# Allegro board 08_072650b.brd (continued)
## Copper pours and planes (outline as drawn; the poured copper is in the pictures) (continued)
UNNAMED_41_ADLTM4709_I15_VIN11 on TOP: 190.14,220.27 197.49,220.27 198.15,220.93 198.15,222.68 197.76,223.06 196.42,223.06 195.43,222.1 193.65,222.1 193.24,221.69 191.85,221.69 191.08,222.45 190.91,222.68 190.27,222.68 189.89,222.3 189.89,220.52
UNNAMED_41_ADLTM4709_I15_VIN11 on BOTTOM: 189.76,222.43 190.02,222.68 190.91,222.68 191.8,221.79 193.19,221.79 193.45,221.54 193.45,220.27 193.19,220.01 190.14,220.01 189.76,220.4
UNNAMED_41_ADLTM4709_I15_VIN21 on TOP: 191.29,218.62 191.29,217.98 191.54,217.73 193.32,217.73 193.45,217.86 195.73,217.86 196.11,218.24 197.89,218.24 198.15,217.98 198.15,216.46 197.89,216.2 190.14,216.2 189.89,216.46 189.89,218.36 190.14,218.62
UNNAMED_41_ADLTM4709_I15_VIN21 on BOTTOM: 190.27,216.08 193.32,216.08 193.45,216.2 193.45,217.73 193.38,217.79 191.73,217.79 191.54,217.98 191.03,218.62 190.14,218.62 189.89,218.36 189.89,216.46
UNNAMED_41_ADLTM4709_I15_VIN31 on TOP: 191.75,213.79 191.16,214.35 189.77,214.3 189.76,214.3 189.76,212.14 190.65,211.25 197.43,211.25 197.43,213.79
UNNAMED_41_ADLTM4709_I15_VIN31 on BOTTOM: 189.76,214.05 190.27,214.55 191.03,214.55 191.92,213.66 192.05,213.49 193.85,213.49 193.85,211.66 190.14,211.63 189.76,212.01
UNNAMED_41_ADLTM4709_I15_VOUT11 on BOTTOM: 189.76,220.52 189.76,222.3 189.51,222.55 188.62,222.55 187.99,221.92 187.6,221.92 187.22,222.3 186.59,222.3 185.57,223.32 185.57,224.31 178.74,224.31 178.74,221.51 184.2,221.51 185.32,220.4 189.64,220.4
UNNAMED_41_ADLTM4709_I15_VOUT21 on BOTTOM: 187.12,218.06 187.22,217.98 187.35,217.86 187.99,217.86 188.62,218.49 189.64,218.49 189.76,218.36 189.76,216.33 189.51,216.08 187.48,216.08 186.84,215.44 181.51,215.44 181.18,215.77 178.31,215.77 178.31,218.06
UNNAMED_41_ADLTM4709_I15_VOUT31 on BOTTOM: 178.41,211.68 185.5,211.68 187.6,213.79 188.11,213.79 188.37,214.05 188.37,214.43 188.62,214.68 189.76,214.68 189.89,214.55 189.89,209.35 178.41,209.35
UNNAMED_42_ADLTM4709_I91_VOUT11 on BOTTOM: 171.3,251.31 161.87,251.31 161.87,255.85 161.85,255.85 161.85,259.16 164.44,261.75 164.44,262.86 164.29,263.02 163.86,263.02 163.63,263.25 163.63,264.34 163.8,264.52 165.76,264.52 165.99,264.29 165.99,260.3 164.85,259.16 164.85,255.91 167.87,255.91 167.87,259.13 168.41,259.68 168.41,262.86 168.26,263.02 167.83,263.02 167.6,263.25 167.6,264.34 167.73,264.46 169.79,264.46 169.96,264.29 169.96,261.95 171.3,260.62
UNNAMED_43_ADLTM4702_I295_VOSNS on TOP: 115.16,272.82 111.1,272.82 110.85,272.57 110.85,270.66 110.46,270.28 107.92,270.28 107.39,270.81 107.39,271.89 107.67,272.16 108.33,272.16 108.43,272.19 108.43,272.69 108.31,272.82 103.99,272.82 103.61,272.44 103.61,262.64 104.5,261.75 114.86,261.75 115.54,262.43 115.54,272.44
UNNAMED_43_ADLTM4709_I340_VIN11 on TOP: 104.23,255.47 104.23,248.96 103.2,247.93 103.2,247.19 103.23,247.19 103.53,246.89 113.69,246.89 114.83,248.03 114.83,255.47
UNNAMED_43_ADLTM4709_I340_VIN11 on BOTTOM: 106.07,250.24 105.82,250.49 104.67,250.49 104.42,250.24 104.42,248.89 103.28,247.75 103.28,247.19 103.53,246.94 105.44,246.94 106.45,247.95 106.45,248.18 106.07,248.56
UNNAMED_43_ADLTM4709_I340_VIN11 on BOTTOM: 114.27,250.49 112.88,250.49 112.42,250.04 112.42,248.97 111.68,248.23 111.68,246.99 113.87,246.99 114.27,247.4
UNNAMED_43_ADLTM4709_I340_VIN11 on BOTTOM: 110.03,250.27 109.78,250.52 108.64,250.52 108.38,250.27 108.38,249.12 107.24,247.98 107.24,247.22 107.49,246.96 109.4,246.96 110.03,247.6
UNNAMED_43_CAP_I177_N2 on TOP: 84.35,213.73 84.1,213.99 81.56,213.99 81.31,213.73 81.31,212.01 82.55,210.76 84.07,210.76 84.35,211.04
UNNAMED_43_CAP_I177_N2 on BOTTOM: 81.74,211.8 82.73,211.8 82.98,212.06 82.98,213.68 82.73,213.94 81.74,213.94 81.48,213.68 81.48,212.06
UNNAMED_43_CAP_I257_N2 on TOP: 71.02,213.59 70.76,213.84 68.22,213.84 67.97,213.59 67.97,211.86 69.22,210.62 70.74,210.62 71.02,210.9
UNNAMED_43_CAP_I257_N2 on BOTTOM: 68.4,211.66 69.39,211.66 69.65,211.91 69.65,213.54 69.39,213.79 68.4,213.79 68.15,213.54 68.15,211.91
UNNAMED_43_CAPSP_I428_N2 on BOTTOM: 69.24,215.85 74.09,215.83 74.09,219.08 70.46,219.1 70.46,217.17 69.24,217.17
UNNAMED_43_IND_I175_N1 on TOP: 84.71,213.94 84.71,211.66 87.63,211.66 87.63,213.94
UNNAMED_43_IND_I260_N1 on TOP: 71.32,213.79 71.32,211.68 74.22,211.68 74.22,213.79
UNNAMED_51_ADP7112_I30_EN on BOTTOM: 90.55,261.67 90.55,258.55 91.67,258.55 92.76,259.64 95.17,259.64 95.17,261.67
UNNAMED_51_ADP7159V2_I59_EN on BOTTOM: 88.29,260.65 90.47,260.65 90.47,262.38 92.66,262.38 92.66,264.57 88.29,264.57
UNNAMED_51_ADP7159V2_I59_VOUT1 on BOTTOM: 89.15,252.7 89.15,258.37 87.68,258.37 87.68,252.7
UNNAMED_51_CAP_I15_N1 on BOTTOM: 83.67,265.89 94.16,265.89 94.16,267.97 88.57,267.97 88.57,278.89 83.67,278.89
VCMD_A on BOTTOM: 174.22,202.44 174.22,201.09 176.07,201.09 176.07,202.44
VCMD_A on L13_GROUND: 136.53,140.03 109.8,140.03 109.78,140 109.78,129.51 109.83,129.46 113.84,129.46 113.84,124.76 106.11,124.76 106.08,143.74 133.4,143.74 133.4,179.53 156.08,202.21 176.16,202.21 176.17,200.81 157.71,200.81 136.45,179.55 136.53,144.4
VCMD_B on BOTTOM: 177.01,209.09 177.01,207.98 179.37,207.98 179.37,209.09
VCMD_B on L13_GROUND: 176.94,209.04 180.37,209.04 180.37,189.38 180.42,189.38 180.42,183.16 170.08,183.16 170.08,161.57 158.32,149.81 158.32,142.41 140.58,124.66 130.76,124.66 130.73,124.69 130.73,129.13 130.9,129.3 141.36,129.3 154.58,142.52 154.58,152.27 166.98,164.67 166.98,185.75 176.94,185.75
VNEGM1P0_ADC on BOTTOM: 204.34,164.95 204.34,162.59 206.83,162.59 206.83,168.78 203.43,168.78 203.43,167.72 202.69,166.98 202.29,166.98 201.85,166.55 201.85,165.35 202.06,165.15 204.14,165.15
VNEGM1P0_ADC on L11_POWER: 134.98,175.39 172.01,175.39 177.47,169.93 206.77,169.93 206.74,162.84 204.83,162.84 203.84,163.83 199.57,163.83 197.31,161.57 151.82,161.57 130.77,140.53 130.76,130.89 121.77,130.94 113.89,130.99 113.89,140 113.97,140.08 113.97,154.38 ; 1 cut-out
VNEGM1P0_ADC_I+ on TOP: 206.93,160.27 209.11,160.28 209.11,160.25 214.02,160.25 214.02,167.18 207.29,167.18 207.29,164.36 206.93,164.01
VNEGM1P0_ADC_I+ on BOTTOM: 207.31,163.53 207.31,158.95 214.93,158.95 214.93,162.74 213.82,163.86 207.65,163.86
VNEGM1P0_DAC on BOTTOM: 204.5,152.15 206.1,152.15 206.1,158.04 203.2,158.04 203.07,157.91 203.07,156.41 201.57,156.41 200.91,155.75 200.91,154.94 201.17,154.69 203.68,154.69 203.71,154.71 203.71,152.58 204.5,152.58
VNEGM1P0_DAC on L5_MIXED: 196.52,100.94 192.73,97.26 192.73,96.32 187.88,91.47 177.86,91.47 172.03,97.29 170.64,97.29 146.38,121.55 132.54,121.55 132.54,123.33 132.03,123.33 132.03,123.93 128.47,123.93 128.47,130.3 132.03,130.3 132.03,131.2 132.49,131.2 132.49,132.87 132.46,133.12 132.46,134.12 134.82,134.12 135.2,133.74 142.7,133.74 163.27,154.32 172.79,154.32 178.78,160.3 186.06,160.3 196.52,149.83
VNEGM1P0_DAC on L5_MIXED: 65.28,92.95 58.42,92.95 53.47,97.9 50.65,100.74 48.64,102.73 47.5,103.87 47.5,157.66 53.57,163.73 56.48,163.73 56.52,163.69 66.29,163.69 73.03,156.96 74.42,156.96 97.32,134.06 112.14,134.06 112.14,130.92 113.03,130.92 113.03,130.16 116.33,130.16 116.33,123.81 113.03,123.81 113.03,123.05 112.14,123.05 112.14,121.02 101.57,121.02 80.49,99.94 72.26,99.94
VNEGM1P0_DAC on L22_MIXED: 189.56,170.38 189.61,170.33 192.02,170.33 206.2,156.16 206.2,154.25 205.49,153.54 205.49,150.93 200.99,146.43 196.52,142.83 196.52,112.78 193.75,112.78 192.35,111.38 192.35,94.61 188.16,90.42 176.48,90.42 146.13,120.78 132.54,120.78 132.54,123.19 131.65,123.19 131.65,123.95 128.35,123.95 128.35,130.05 132.41,130.05 132.41,134.11 133.68,134.11 135.08,135.51 135.08,143.21 139.89,148.02 151.3,148.02 155.7,152.43 155.7,154.15 132.72,177.14 112.22,177.14 90.5,155.42 90.5,151.64 93.55,148.58 104.87,148.58 109.55,143.94 109.55,134.11 112.22,134.11 112.22,130.05 116.15,130.05 116.15,123.95 112.98,123.95 112.98,123.19 111.96,123.19 111.96,121.16 98.5,121.16 70.05,92.71 58.52,92.71 46.81,104.42 46.81,155.88 60.07,169.14 66.37,169.14 92.68,195.45 160.1,195.45 174.24,181.31 174.24,172.82 176.68,170.38
VNEGM1P0_DAC_I+ on TOP: 206.48,150.7 212.9,150.7 213.18,150.98 213.18,156.51 206.98,156.51 206.98,154.03 206.48,153.52
VNEGM1P0_DAC_I+ on BOTTOM: 214.48,147.45 206.38,147.45 206.38,153.16 206.62,153.4 212.79,153.4 214.48,151.71

Small or netless copper shapes (teardrops, artwork), in the pictures only: 14 on TOP, 4 on BOTTOM

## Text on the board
Ref Des/Silkscreen Bottom: I_MEAS
Ref Des/Silkscreen Top: PWR GOOD | I_MEAS | I_SENSE | ON | OFF | 0P8V | 2P8V | 3P6V | 1P3VA | 5P7V | 12POV | 1P8VD | 1POVD | 0P8VDAC | 1P8V_MCS | NEG2P3V | 1P0VDAC | 2P1V | ADF4382 PLL LOCK | PSM FAULT | PSM ALERT | AD9084-FMCC-EBZ | 08-072650 REV B
XSECTION_CHART: * SURFACE - AIR 0 MIL | L1 CONDUCTOR - PLATED_COPPER_FOIL 1.75 MIL | * DIELECTRIC - I-TERA_MT40 4.25 MIL | L2 CONDUCTOR - PLATED_COPPER_FOIL 0.85 MIL | * DIELECTRIC - I-TERA_MT40 5 MIL | L3 CONDUCTOR - COPPER 0.6 MIL | * DIELECTRIC - I-TERA_MT40 3.5 MIL | L4 CONDUCTOR - COPPER 0.6 MIL | * DIELECTRIC - I-TERA_MT40 3.93 MIL | L5 CONDUCTOR - COPPER 1.2 MIL | * DIELECTRIC - 370HR 3 MIL | L6 CONDUCTOR - COPPER 1.2 MIL | * DIELECTRIC - I-TERA_MT40 3.84 MIL | L7 CONDUCTOR - COPPER 1.2 MIL | * DIELECTRIC - 370HR 2 MIL | L8 CONDUCTOR - COPPER 1.2 MIL | L9 CONDUCTOR - COPPER 1.2 MIL | L10 CONDUCTOR - COPPER 1.2 MIL | * DIELECTRIC - I-TERA_MT40 4.21 MIL | L11 CONDUCTOR - COPPER 2.6 MIL | L12 CONDUCTOR - COPPER 2.6 MIL | * DIELECTRIC - I-TERA_MT40 4.2 MIL | L13 CONDUCTOR - COPPER 2.6 MIL | L14 CONDUCTOR - COPPER 2.6 MIL | L15 CONDUCTOR - COPPER 2.6 MIL | L16 CONDUCTOR - COPPER 2.6 MIL | L17 CONDUCTOR - COPPER 1.2 MIL | L18 CONDUCTOR - COPPER 1.2 MIL | * DIELECTRIC - I-TERA_MT40 3.83 MIL | L19 CONDUCTOR - COPPER 1.2 MIL | L20 CONDUCTOR - COPPER 1.2 MIL | * DIELECTRIC - I-TERA_MT40 3.72 MIL | L21 CONDUCTOR - COPPER 1.2 MIL | L22 CONDUCTOR - COPPER 1.2 MIL | L23 CONDUCTOR - COPPER 0.6 MIL | L24 CONDUCTOR - COPPER 0.6 MIL | L25 CONDUCTOR - PLATED_COPPER_FOIL 0.85 MIL | * DIELECTRIC - I-TERA_MT40 4.26 MIL | L26 CONDUCTOR - PLATED_COPPER_FOIL 1.75 MIL | DESIGN CROSS SECTION CHART | ___________________________ | TOTAL THICKNESS 122.93 MIL | 1-26 | 1-2 | 2-3 | 24-25 | 25-26 | B1-2-3 | B1-21-22 | B26-25-24
PAGE_OUTLINE: B | 13OCT23 | A.L. | FOR CONTROLLED IMPEDANCE VALUES | PLEASE REFER TO_STACKUP REPORT IN DATA PACKAGE
User.17: L2 GROUND | 08-      -07
User.18: L3 SIGNAL | 08-      -08
User.19: L4 GROUND | 08-      -09
User.20: L5 MIXED | 08-      -10
User.24: L6 GROUND | 08-      -11
User.25: L7 POWER | 08-      -12
User.26: L8 GROUND | 08-      -13
User.27: L9 POWER | 08-      -14
User.28: L10 GROUND | 08-      -15
User.29: L11 POWER | 08-      -16
User.30: L12 GROUND | 08-      -17
User.31: L13 GROUND | 08-      -18
User.32: L14 POWER | 08-      -19
User.33: L15 GROUND | 08-      -20
User.34: L16 POWER | 08-      -21
User.35: L17 GROUND | 08-      -22
User.36: L18 POWER | 08-      -23
User.37: L19 GROUND | 08-      -24
User.38: L20 POWER | 08-      -25
User.39: L21 GROUND | 08-      -26
User.40: L22 MIXED | 08-      -27
User.41: L23 GROUND | 08-      -28
User.42: L24 SIGNAL | 08-      -29
User.43: L25 GROUND | 08-      -3
User.45: FILLED NOTE 15 | FIGURE | BD_SIZE | 22.0 | FINISHED_SIZE | 7.0 | 8.0 | 6.0 | 10.0 | 12.0 | 18.0 | 25.0 | 35.0 | 40.0 | 60.0 | 65.0 | 70.0 | 75.0 | 50.0 | 63.0 | 118.0 | 125.0 | 160.0 | 41.0x26.0 | 47.0x28.0 | 225.0x110.0 | ROTATION | - | MNC_LAYER | L3_SIGNAL | L22_MIXED | L24_SIGNAL | 0.000 | 90.000 | BACKDRILL: TOP to L2_GROUND | ALL UNITS ARE IN MILS | BACKDRILL: TOP to L21_GROUND | BACKDRILL: BOTTOM to L25_GROUND | DRILL CHART: L25_GROUND to BOTTOM | DRILL CHART: L24_SIGNAL to L25_GROUND | DRILL CHART: L2_GROUND to L3_SIGNAL | DRILL CHART: TOP to L2_GROUND | TOLERANCE_DRILL | +3.0/-0.0 | DRILL CHART: TOP to BOTTOM | MAX_DEPTH | 12.2 | 101.68 | 12.21 | +3.0/-3.0 | +5.0/-5.0 | +0.0/-0.0 | MFG_STUB | PLATED | NON-PLATED | QTY | 32 | 28 | 26 | 866 | 217 | 3898 | 4096 | 5 | 2377 | 4466 | 843 | 12 | 4 | 8 | 25 | 60 | 2 | 6 | 7 | DETAIL/NOTE | DETAIL-A
